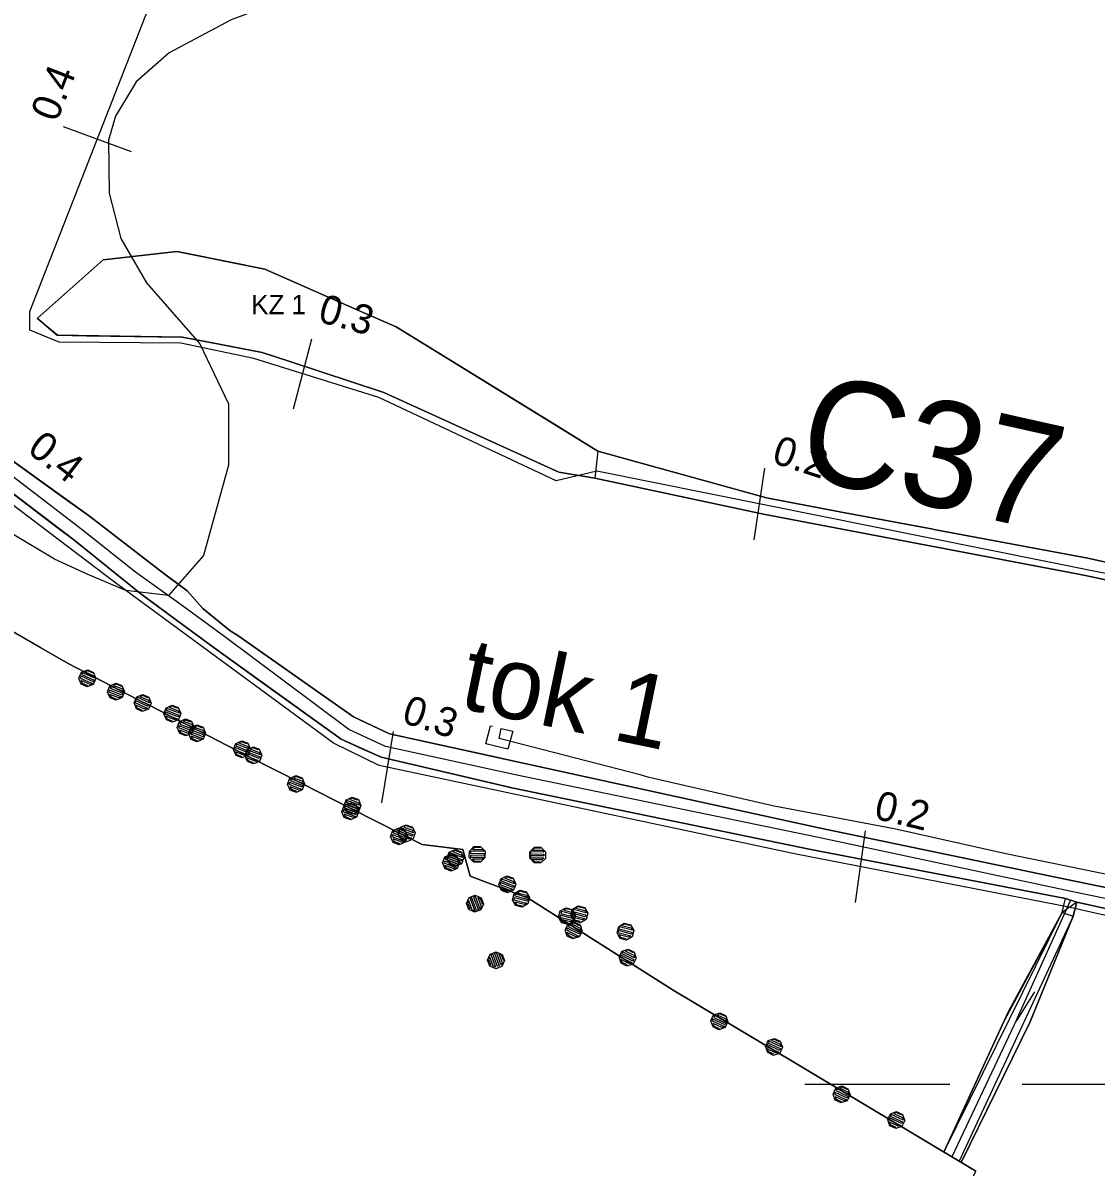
# Model space of a CAD drawing. Extents: x -645676 to -642474, y -1077513 to -1072613.
# Drawn here: x -644954.9 to -644732.8, y -1075319 to -1075082.2 of the extents above; entities that cross this region are included whole.
import ezdxf

# ---------------------------------------------------------------- set-up
doc = ezdxf.new("R2010")
doc.units = 0
for name, color, linetype in [('ELEKTRO', 7, 'Continuous'), ('KRAJ_ZELEN_STAV', 7, 'Continuous'), ('Krajinn__zele____popis___stav', 7, 'Continuous'), ('KULTURY_STAV', 7, 'Continuous'), ('KULTURY_ZNACKY', 7, 'Continuous'), ('OBVOD_PU', 7, 'Continuous'), ('PC_NAVRH', 7, 'Continuous'), ('PC_POPIS_NAVRH', 7, 'Continuous'), ('PC_STAN_NAVRH', 7, 'Continuous'), ('PLYNOVOD', 7, 'Continuous'), ('SPRAV_HR_STAV', 7, 'Continuous'), ('Vodn__plocha___st_vaj_c_', 7, 'Continuous'), ('Vodn__tok', 7, 'Continuous'), ('Vodn__tok___zatrubn_n_', 7, 'Continuous'), ('VRSTEVNICE', 7, 'Continuous')]:
    doc.layers.add(name, color=color, linetype=linetype)

# ---------------------------------------------------------------- blocks, each defined once
blk = doc.blocks.new('$944')
blk.add_line((0, 1.5), (0, -1.5))
blk = doc.blocks.new('8$0300')
for p, q in [((-7.5, 0), (-1.5, 0)), ((1.5, 0), (7.5, 0))]:
    blk.add_line(p, q)
blk = doc.blocks.new('2$0620')
for points in [[(-1.07, 0.32), (-0.88, 0.13), (-0.88, -0.14), (-1.07, -0.33), (-1.34, -0.33), (-1.53, -0.14), (-1.53, 0.13), (-1.34, 0.32), (-1.07, 0.32), (-1.08, 0.28), (-1.32, 0.28), (-1.4, 0.2), (-1, 0.2), (-0.92, 0.12), (-1.48, 0.12), (-1.48, 0.04), (-0.92, 0.04), (-0.92, -0.04), (-1.48, -0.04), (-1.48, -0.12), (-0.92, -0.12), (-1, -0.2), (-1.4, -0.2), (-1.32, -0.28), (-1.08, -0.28)], [(1.43, 0.32), (1.62, 0.13), (1.62, -0.14), (1.43, -0.33), (1.16, -0.33), (0.97, -0.14), (0.97, 0.13), (1.16, 0.32), (1.43, 0.32), (1.4, 0.28), (1.16, 0.28), (1.08, 0.2), (1.48, 0.2), (1.56, 0.12), (1, 0.12), (1, 0.04), (1.56, 0.04), (1.56, -0.04), (1, -0.04), (1, -0.12), (1.56, -0.12), (1.48, -0.2), (1.08, -0.2), (1.16, -0.28), (1.4, -0.28)]]:
    blk.add_lwpolyline(points)

msp = doc.modelspace()

# ---------------------------------------------------------------- linework, layer by layer
at = {"layer": 'ELEKTRO'}
msp.add_line((-644749.32, -1075288.75), (-644745.52, -1075282.69), dxfattribs=at)
at = {"layer": 'KRAJ_ZELEN_STAV'}
msp.add_lwpolyline([(-644947.78, -1075146.86), (-644951.94, -1075143.38), (-644938.27, -1075131.27), (-644923.08, -1075129.52), (-644904.88, -1075133.21), (-644877.67, -1075145.14), (-644835.95, -1075170.81), (-644836.56, -1075176.4), (-644844, -1075175.21), (-644880.23, -1075158.7), (-644905.37, -1075150.42), (-644921.95, -1075147.25), (-644947.78, -1075146.86)], dxfattribs=at)
at = {"layer": 'KULTURY_STAV'}
for points in [[(-644684.51, -1075207.35), (-644735.38, -1075196.48), (-644801.32, -1075183.93), (-644836.56, -1075176.4), (-644844, -1075175.21), (-644880.24, -1075158.7), (-644899.89, -1075152.22), (-644905.37, -1075150.42), (-644916.06, -1075148.38), (-644921.95, -1075147.25), (-644941.78, -1075146.95), (-644947.78, -1075146.86), (-644947.81, -1075146.83), (-644951.89, -1075143.42), (-644951.94, -1075143.38), (-644938.27, -1075131.27), (-644923.08, -1075129.52), (-644920.54, -1075130.04), (-644904.88, -1075133.21), (-644885.63, -1075141.65), (-644877.67, -1075145.14), (-644844.5, -1075165.55), (-644839.17, -1075168.83), (-644835.95, -1075170.81), (-644801.04, -1075180.52), (-644785.51, -1075183.44), (-644767.31, -1075186.86), (-644765.62, -1075187.17), (-644734.54, -1075193.01), (-644683.98, -1075204.21)], [(-644683.98, -1075204.21), (-644734.54, -1075193.01), (-644765.62, -1075187.17), (-644767.31, -1075186.86), (-644785.51, -1075183.44), (-644801.04, -1075180.52), (-644835.95, -1075170.81), (-644839.17, -1075168.83), (-644844.5, -1075165.55), (-644877.67, -1075145.14), (-644885.63, -1075141.65), (-644904.88, -1075133.21), (-644920.54, -1075130.04), (-644923.08, -1075129.52), (-644938.27, -1075131.27), (-644951.94, -1075143.38), (-644951.89, -1075143.42), (-644947.81, -1075146.83), (-644947.78, -1075146.86), (-644941.78, -1075146.95), (-644921.95, -1075147.25), (-644916.06, -1075148.38), (-644905.37, -1075150.42), (-644899.89, -1075152.22), (-644880.24, -1075158.7), (-644844, -1075175.21), (-644836.56, -1075176.4), (-644801.32, -1075183.93), (-644735.38, -1075196.48), (-644684.51, -1075207.35)], [(-644966.6, -1075165.99), (-644946.66, -1075180.34), (-644941.15, -1075184.31), (-644926.62, -1075195.45), (-644924.35, -1075197.17), (-644920.94, -1075199.74), (-644917.66, -1075203.39), (-644912, -1075208.03), (-644910.45, -1075208.96), (-644904.33, -1075213.27), (-644886.49, -1075225.84), (-644883.71, -1075227.15), (-644879.03, -1075229.35), (-644860.4, -1075233.4), (-644852.65, -1075235.09), (-644790.18, -1075248.74), (-644741.2, -1075258.95), (-644690.73, -1075269.38)], [(-644690.73, -1075269.38), (-644741.2, -1075258.95), (-644790.18, -1075248.74), (-644852.65, -1075235.09), (-644860.4, -1075233.4), (-644879.03, -1075229.35), (-644883.71, -1075227.15), (-644886.49, -1075225.84), (-644904.33, -1075213.27), (-644910.45, -1075208.96), (-644912, -1075208.03), (-644917.66, -1075203.39), (-644920.94, -1075199.74), (-644924.35, -1075197.17), (-644926.62, -1075195.45), (-644941.15, -1075184.31), (-644946.66, -1075180.34), (-644966.6, -1075165.99)], [(-644970.16, -1075169.63), (-644947.6, -1075186.77), (-644944.38, -1075189.22), (-644930.54, -1075200.39), (-644925.51, -1075204.04), (-644924.41, -1075204.84), (-644915.35, -1075211.56), (-644905.39, -1075218.71), (-644889.02, -1075230.45), (-644884.7, -1075232.41), (-644880.8, -1075234.17), (-644861.34, -1075238.7), (-644853.72, -1075240.48), (-644791.85, -1075253.25), (-644739.12, -1075263.4), (-644736.8, -1075264.15), (-644739.87, -1075266.31), (-644751.83, -1075288.71), (-644764.35, -1075315.85), (-644795.04, -1075297.48), (-644820.35, -1075282.33), (-644850.33, -1075263.32), (-644852.84, -1075262.37), (-644862.38, -1075258.74), (-644863.9, -1075253.24), (-644872.26, -1075252.25), (-644876.28, -1075250.21), (-644887.03, -1075244.75), (-644897.16, -1075239.61), (-644908.34, -1075233.93), (-644928.8, -1075223.41), (-644931.18, -1075222.19), (-644945.57, -1075214.79), (-644951.22, -1075211.54), (-644979.55, -1075195.21)], [(-644692.33, -1075274.04), (-644736.8, -1075264.15), (-644739.12, -1075263.4), (-644791.85, -1075253.25), (-644853.72, -1075240.48), (-644861.34, -1075238.7), (-644880.8, -1075234.17), (-644884.7, -1075232.41), (-644889.02, -1075230.45), (-644905.39, -1075218.71), (-644915.35, -1075211.56), (-644924.41, -1075204.84), (-644925.51, -1075204.04), (-644930.54, -1075200.39), (-644944.38, -1075189.22), (-644947.6, -1075186.77), (-644970.16, -1075169.63)], [(-644851.08, -1075513.74), (-644779.52, -1075365.17), (-644777.84, -1075361.69), (-644757.68, -1075319.84), (-644760.71, -1075318.03), (-644746.53, -1075289.08), (-644737.59, -1075267.05), (-644736.8, -1075264.15), (-644692.33, -1075274.04), (-644655.11, -1075281.83), (-644643, -1075284.37), (-644621.33, -1075289.98), (-644615.66, -1075293.05), (-644612.56, -1075292.62), (-644616.89, -1075364.66), (-644616.92, -1075365.04), (-644618.52, -1075388.88), (-644622.17, -1075442.97), (-644622.41, -1075446.47), (-644626.67, -1075468.75), (-644631.36, -1075486.14), (-644660.63, -1075594.71)], [(-644736.8, -1075264.15), (-644737.59, -1075267.05), (-644746.53, -1075289.08), (-644760.71, -1075318.03), (-644761.14, -1075317.77), (-644764.35, -1075315.85), (-644751.83, -1075288.71), (-644750.93, -1075286.77), (-644739.87, -1075266.31), (-644739.12, -1075263.4), (-644736.8, -1075264.15)]]:
    msp.add_lwpolyline(points, dxfattribs=at)
at = {"layer": 'OBVOD_PU'}
msp.add_lwpolyline([(-644851.08, -1075513.74), (-644779.52, -1075365.17), (-644777.84, -1075361.69), (-644757.68, -1075319.84), (-644795.04, -1075297.48), (-644820.35, -1075282.33), (-644850.33, -1075263.32), (-644852.84, -1075262.37), (-644862.38, -1075258.74), (-644863.9, -1075253.24), (-644872.26, -1075252.25), (-644876.28, -1075250.21), (-644887.03, -1075244.75), (-644897.16, -1075239.61), (-644908.34, -1075233.93), (-644928.8, -1075223.41), (-644931.18, -1075222.19), (-644945.57, -1075214.79), (-644951.22, -1075211.54), (-644979.55, -1075195.21)], dxfattribs=at)
at = {"layer": 'PC_NAVRH'}
for points in [[(-644606.41, -1075221.19), (-644836.11, -1075174.98), (-644844.56, -1075176.95), (-644881.27, -1075159.75), (-644907.13, -1075151.69), (-644922.26, -1075148.52), (-644947.39, -1075148.27), (-644953.49, -1075145.83), (-644953.49, -1075141.93), (-644894.93, -1074992.28), (-644829.47, -1074825.22)], [(-644615.94, -1075324.38), (-644614.35, -1075298.06), (-644618.37, -1075293.21), (-644622.69, -1075291.24), (-644738.79, -1075265.15), (-644794.9, -1075254.19), (-644881.17, -1075235.85), (-644890.64, -1075231.29), (-644935.93, -1075197.93), (-645029.58, -1075127.01), (-645122.98, -1075056.71), (-645236.69, -1074970.28), (-645321.72, -1074906.75)]]:
    msp.add_lwpolyline(points, dxfattribs=at)
at = {"layer": 'PLYNOVOD'}
msp.add_lwpolyline([(-644726.18, -1075259.33), (-644751.5, -1075254.12), (-644774.62, -1075249.01), (-644799.44, -1075244.28), (-644825.29, -1075238.34), (-644827.15, -1075237.83), (-644856.38, -1075230.29), (-644855.97, -1075228.19), (-644853.55, -1075228.78), (-644854.57, -1075232.51), (-644859.13, -1075231.4), (-644858.16, -1075227.66), (-644857.72, -1075227.71)], dxfattribs=at)
at = {"layer": 'SPRAV_HR_STAV'}
for p, q in [((-644979.55, -1075195.21), (-644951.22, -1075211.54)), ((-644951.22, -1075211.54), (-644945.57, -1075214.79)), ((-644945.57, -1075214.79), (-644931.18, -1075222.19)), ((-644931.18, -1075222.19), (-644928.8, -1075223.41)), ((-644928.8, -1075223.41), (-644908.34, -1075233.93)), ((-644908.34, -1075233.93), (-644897.16, -1075239.61)), ((-644897.16, -1075239.61), (-644887.03, -1075244.75)), ((-644887.03, -1075244.75), (-644876.28, -1075250.21)), ((-644876.28, -1075250.21), (-644872.26, -1075252.25)), ((-644872.26, -1075252.25), (-644863.9, -1075253.24)), ((-644863.9, -1075253.24), (-644862.38, -1075258.74)), ((-644862.38, -1075258.74), (-644852.84, -1075262.37)), ((-644852.84, -1075262.37), (-644850.33, -1075263.32)), ((-644850.33, -1075263.32), (-644820.35, -1075282.33)), ((-644820.35, -1075282.33), (-644795.04, -1075297.48)), ((-644795.04, -1075297.48), (-644757.68, -1075319.84))]:
    msp.add_line(p, q, dxfattribs=at)
at = {"layer": 'Vodn__plocha___st_vaj_c_'}
for points in [[(-644966.6, -1075165.99), (-644941.15, -1075184.31), (-644926.62, -1075195.45), (-644920.94, -1075199.74), (-644917.66, -1075203.39), (-644912, -1075208.03), (-644910.45, -1075208.96), (-644886.49, -1075225.84), (-644879.03, -1075229.35), (-644852.65, -1075235.09), (-644790.18, -1075248.74), (-644741.2, -1075258.95), (-644690.73, -1075269.38)], [(-644690.73, -1075269.38), (-644741.2, -1075258.95), (-644790.18, -1075248.74), (-644852.65, -1075235.09), (-644879.03, -1075229.35), (-644886.49, -1075225.84), (-644910.45, -1075208.96), (-644912, -1075208.03), (-644917.66, -1075203.39), (-644920.94, -1075199.74), (-644926.62, -1075195.45), (-644941.15, -1075184.31), (-644966.6, -1075165.99)], [(-644692.33, -1075274.04), (-644736.8, -1075264.15), (-644739.12, -1075263.4), (-644791.85, -1075253.25), (-644853.72, -1075240.48), (-644880.8, -1075234.17), (-644889.02, -1075230.45), (-644915.35, -1075211.56), (-644924.41, -1075204.84), (-644930.54, -1075200.39), (-644944.38, -1075189.22), (-644970.16, -1075169.63)], [(-644970.16, -1075169.63), (-644944.38, -1075189.22), (-644930.54, -1075200.39), (-644924.41, -1075204.84), (-644915.35, -1075211.56), (-644889.02, -1075230.45), (-644880.8, -1075234.17), (-644853.72, -1075240.48), (-644791.85, -1075253.25), (-644739.12, -1075263.4), (-644736.8, -1075264.15), (-644692.33, -1075274.04)], [(-644739.87, -1075266.31), (-644737.59, -1075267.05), (-644761.14, -1075317.77), (-644764.35, -1075315.85), (-644739.87, -1075266.31)]]:
    msp.add_lwpolyline(points, dxfattribs=at)
msp.add_lwpolyline([(-644739.87, -1075266.31), (-644739.12, -1075263.4), (-644736.8, -1075264.15), (-644737.59, -1075267.05), (-644746.53, -1075289.08), (-644760.71, -1075318.03), (-644761.14, -1075317.77), (-644764.35, -1075315.85), (-644750.93, -1075286.77)], close=True, dxfattribs=at)
at = {"layer": 'Vodn__tok'}
msp.add_line((-644749.15, -1075288.23), (-644762.66, -1075316.86), dxfattribs=at)
for points in [[(-644737.28, -1075262.07), (-644790.63, -1075250.71), (-644852.68, -1075237.9), (-644879.87, -1075231.93), (-644887.46, -1075228.4), (-644913.43, -1075209.05), (-644922.62, -1075202.32), (-644931.59, -1075195.91), (-644942.63, -1075187.1), (-644967.94, -1075167.74), (-644997, -1075145.82), (-645040.36, -1075114.96), (-645089.98, -1075076.71), (-645130.46, -1075044.8), (-645189.79, -1075000.02), (-645239.14, -1074962.61), (-645275.37, -1074935.26), (-645317.56, -1074903.59), (-645325.71, -1074895.16), (-645357.55, -1074846.07), (-645371.25, -1074825.24)], [(-644620.31, -1075287.58), (-644642.19, -1075282.08), (-644691.33, -1075271.61), (-644737.28, -1075262.07)]]:
    msp.add_lwpolyline(points, dxfattribs=at)
at = {"layer": 'Vodn__tok___zatrubn_n_'}
msp.add_line((-644749.15, -1075288.23), (-644738.02, -1075263.67), dxfattribs=at)
at = {"layer": 'VRSTEVNICE'}
for points in [[(-644877.1, -1074921.7), (-644865.69, -1074953.4), (-644861.7, -1074967.08), (-644857.43, -1074985.3), (-644856.14, -1074998.98), (-644856.29, -1075008.09), (-644858, -1075026.32), (-644859.85, -1075035.44), (-644864.69, -1075049.11), (-644872.52, -1075060.93), (-644875.51, -1075064.06), (-644882.35, -1075069.48), (-644890.47, -1075073.61), (-644911.83, -1075081.58), (-644924.65, -1075088.42), (-644931.48, -1075094.4), (-644935.76, -1075101.52), (-644937.18, -1075106.5), (-644937.04, -1075117.47)], [(-644937.04, -1075117.47), (-644934.62, -1075126.87), (-644929.35, -1075135.99), (-644918.33, -1075148.65), (-644912.38, -1075161.08), (-644912.38, -1075173.76), (-644917.56, -1075192.4), (-644924.8, -1075200.68), (-644933.6, -1075199.65), (-644941.62, -1075196.28), (-644948.35, -1075193.18), (-644965.95, -1075182.7)]]:
    msp.add_lwpolyline(points, dxfattribs=at)

# ---------------------------------------------------------------- block references
at = {"layer": 'KULTURY_ZNACKY', "xscale": 5, "yscale": 5}
msp.add_blockref('8$0300', (-644755.6, -1075301.81), dxfattribs=at)
at = {"layer": 'PC_STAN_NAVRH'}
for p, xscale, yscale, rotation in [((-644939.52, -1075106.23), 5.000000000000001, 4.999999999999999, 69.826687), ((-644897.01, -1075154.84), 5, 5, 165.536701), ((-644802.49, -1075181.75), 5, 5, 171.570307), ((-644879.43, -1075236.22), 5, 4.999999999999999, 170.92905800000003), ((-644781.57, -1075256.8), 5, 4.999999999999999, 171.896762)]:
    msp.add_blockref('$944', p, dxfattribs=dict(at, xscale=xscale, yscale=yscale, rotation=rotation))
at = {"layer": 'SPRAV_HR_STAV'}
for p, xscale, yscale, rotation in [((-644936.05, -1075220.27), 5.000000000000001, 4.999999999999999, -24.14724700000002), ((-644930.01, -1075222.79), 4.999999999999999, 5.000000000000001, -21.406099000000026), ((-644915.61, -1075230.17), 4.999999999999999, 4.999999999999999, -21.33040599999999), ((-644913.24, -1075231.41), 5, 5, -21.402790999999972), ((-644892.74, -1075241.86), 5, 5, -21.119728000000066), ((-644881.55, -1075247.53), 5, 5, -21.089762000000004), ((-644871.43, -1075252.67), 4.999999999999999, 5.000000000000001, -21.113112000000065), ((-644854.88, -1075254.31), 5.000000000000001, 5, -0.5882589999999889), ((-644860.67, -1075258.13), 5, 5, -21.092513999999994), ((-644859.24, -1075270.11), 5.000000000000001, 5, -69.569127), ((-644846.02, -1075264.96), 5, 5, -14.912386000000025), ((-644836.47, -1075268.56), 5.000000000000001, 4.999999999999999, -14.809590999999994), ((-644835.55, -1075272.69), 5.000000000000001, 5, -26.66026099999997), ((-644805.33, -1075291.32), 5, 4.999999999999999, -25.15999700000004), ((-644780.02, -1075306.47), 5, 5, -25.15668899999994)]:
    msp.add_blockref('2$0620', p, dxfattribs=dict(at, xscale=xscale, yscale=yscale, rotation=rotation))

# ---------------------------------------------------------------- texts
at = {"layer": 'Krajinn__zele____popis___stav'}
msp.add_text('KZ 1', height=4, dxfattribs=at).set_placement((-644907.65, -1075142.51))
at = {"layer": 'PC_POPIS_NAVRH'}
msp.add_text('C37', height=22, rotation=347.384, dxfattribs=at).set_placement((-644795.44, -1075175.84))
at = {"layer": 'PC_STAN_NAVRH'}
for s, rotation, p in [('0.4', 68.64, (-644947.9, -1075102.95)), ('0.3', 344.691, (-644894.07, -1075143.99)), ('0.4', 322.174, (-644954.26, -1075170.93)), ('0.2', 341.999, (-644800.16, -1075173.16)), ('0.3', 341.999, (-644876.76, -1075226.88)), ('0.2', 346.525, (-644779, -1075246.81))]:
    msp.add_text(s, height=6, rotation=rotation, dxfattribs=at).set_placement(p)
at = {"layer": 'Vodn__tok'}
msp.add_text('tok 1', height=15, rotation=348.312, dxfattribs=at).set_placement((-644864.93, -1075223.91))

doc.saveas('drawing.dxf')
